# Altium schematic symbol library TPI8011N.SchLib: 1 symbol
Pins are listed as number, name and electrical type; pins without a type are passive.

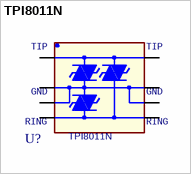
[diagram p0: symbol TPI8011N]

## TPI8011N
designator U?
footprint ST_SO8
pins: 1 TIP, 2 GND, 3 GND1, 4 RING, 5 RING1, 6 GND2, 7 GND3, 8 TIP1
